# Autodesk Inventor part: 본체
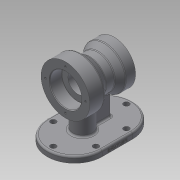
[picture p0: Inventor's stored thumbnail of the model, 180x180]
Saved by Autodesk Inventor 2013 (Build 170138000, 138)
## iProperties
Created: 2020-01
Part Number: 본체
Material: 일반
Document SubType Name: Modeling
Designer: Administrator
Density: 1 g/cm^3
Author: Administrator
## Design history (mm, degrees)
sketch "스케치1"
  geometry: L1 (-40, 0)-(40, 0); L2 (-40, 0)-(-40, 26); L3 (-40, 40)-(-16, 40); L4 (-16, 40)-(-1.103, 27.5); L5 (-1.103, 27.5)-(13.289, 27.5); L6 (13.289, 27.5)-(24, 35); L7 (24, 35)-(40, 35); L8 (40, 35)-(40, 20); L9 (-40, 26)-(-20, 26); L10 (-20, 26)-(-20, 16); L11 (-20, 16)-(23, 16); L12 (23, 16)-(23, 20); L13 (23, 20)-(40, 20); L14 (-40, 26)-(-40, 40); L15 (40, 20)-(40, 0); 2 further points
  constraints: 30 end point, 6 parallel, 4 horizontal, 3 vertical, 2 perpendicular, 1 coincident, 1 midpoint
  dimensions: "d0" = 80 distance of L1.start L1.end; "d2" = 80 diameter of L3 L1; "d3" = 52 diameter of L9 L1; "d4" = 70 diameter of L7 L1; "d5" = 40 diameter of L13 L1; "d6" = 24 distance of L3.start L3.end; "d7" = 20 distance of L2.end L9.end; "d8" = 16 distance of L6.end L7.end; "d9" = 17 distance of L12.end L8.end; "d10" = 55 diameter of L5 L1; "d11" = 40 deg angle of L4 L5; "d12" = 35 deg angle of L6 L5; "d13" = 32 diameter of L11 L1
revolve "회전1" sketch "스케치1" stored, may be unused: angle "d14" = 90 deg
node "작업 평면1"
sketch "스케치2"
  geometry: L1 (-70, 45)-(70, 45); L2 (70, 45)-(70, -45); L3 (70, -45)-(-70, -45); L4 (-70, -45)-(-70, 45); L5 (-70, 45)-(70, -45); L6 (70, 45)-(-70, -45); 4 further points
  constraints: 12 end point, 4 midpoint, 2 coincident, 2 parallel, 1 horizontal, 1 perpendicular
  dimensions: "d16" = 140 distance of L2.end L3.end; "d18" = 90 distance of L3.end L1.start
extrude "돌출1" join sketch "스케치2" distance "d19" = 10; taper "d20" = 0 deg
fillet "모깎기1" dims "d21" = 45
sketch "스케치3" dims "d22" = 32
  geometry: L1 (3.199, 5)-(30, 5); L2 (30, 5)-(30, -5); L3 (30, -5)-(3.199, -5); L4 (3.199, -5)-(3.199, 5); L5 (3.199, 5)-(30, -5); L6 (30, 5)-(3.199, -5); A1 r 45 centre (-25, 0) between (-25, 45) and (-25, -45) reference; 5 further points
  constraints: 12 end point, 4 midpoint, 2 horizontal alignment, 2 parallel, 1 coincident, 1 horizontal, 1 perpendicular, 3 other
  dimensions: "d25" = 13 distance of A1.centre point (-12, 0); "d26" = 30 distance from line of L2 point (0, 0); "d27" = 10 distance of L1.end L2.end
extrude "돌출2" join sketch "스케치3" stored distance "d28" = 10; taper "d29" = 0 deg
sketch "스케치4"
  geometry: L1 (25, 45)-(-25, 45) reference; L2 (-25, -45)-(25, -45) reference; L3 (-25, 35)-(25, 35); L4 (25, -35)-(-25, -35); A1 r 45 centre (25, 0) between (25, -45) and (25, 45) reference; A2 r 45 centre (-25, 0) between (-25, 45) and (-25, -45) reference; A3 r 35 centre (25, 0) between (25, -35) and (25, 35); A4 r 35 centre (-25, 0) between (-25, 35) and (-25, -35); 7 further points
  constraints: 6 point on circle, 4 coincident, 4 end point, 2 centre point, 3 other
  dimensions: "d30" = 10 distance between parallel lines of L1 L3
hole "구멍1" sketch "스케치4" at (-25, 35), (25, 35), (25, -35), (-25, -35), (-60, 0), (60, 0) diameter "d31" = 9; stored, may be unused: countersink angle "d35" = 90 deg, drill point angle "d37" = 0 deg; dims "d32" = 6, "d33" = 4, "d34" = 2, "d36" = 8
sketch "스케치5"
  geometry: C1 r 40 at (0, 0) reference; 1 further point
  constraints: 1 vertical alignment
  dimensions: "d38" = 33 distance of C1.centre point (0, 33)
hole "구멍2" sketch "스케치5" at (0, 33) diameter "d39" = 3.242; stored, may be unused: countersink angle "d43" = 90 deg, drill point angle "d45" = 118 deg; dims "d40" = 9, "d41" = 4, "d42" = 2, "d44" = 11
sketch "스케치6"
  geometry: C1 r 20 at (0, 0) reference; 1 further point
  constraints: 1 vertical alignment
  dimensions: "d49" = 27.5 distance of C1.centre point (0, 27.5)
hole "구멍3" sketch "스케치6" at (0, 27.5) diameter "d50" = 3.242; stored, may be unused: countersink angle "d54" = 90 deg, drill point angle "d56" = 118 deg; dims "d51" = 9, "d52" = 4, "d53" = 2, "d55" = 11
chamfer "모따기1" distance "d60" = 1; stored, may be unused: second distance "d61" = 2, angle "d62" = 45 deg
fillet "모깎기2" dims "d63" = 0.3
fillet "모깎기3" dims "d64" = 3
fillet "모깎기4" dims "d65" = 3
fillet "모깎기5" dims "d66" = 3
fillet "모깎기6" dims "d67" = 3
fillet "모깎기7" dims "d68" = 3
sketch "스케치7"
  geometry: L1 (50, 0)-(0, 0) reference; L2 (-45, 0)-(-45, 7) reference; 2 further points
  constraints: 1 other
  dimensions: "d69" = 70 distance from line of point (25, 4) L2; "d70" = 4 distance from line of L1 point (25, 4)
feature "엠보싱1" sketch "스케치7" dims "d16" = 140, "d18" = 90, "d71" = 0.5, "d72" = 0
node "솔리드1"
pattern_circular "원형 패턴1" dims angle "d47" = 360 deg
pattern_circular "원형 패턴2" dims angle "d58" = 360 deg
